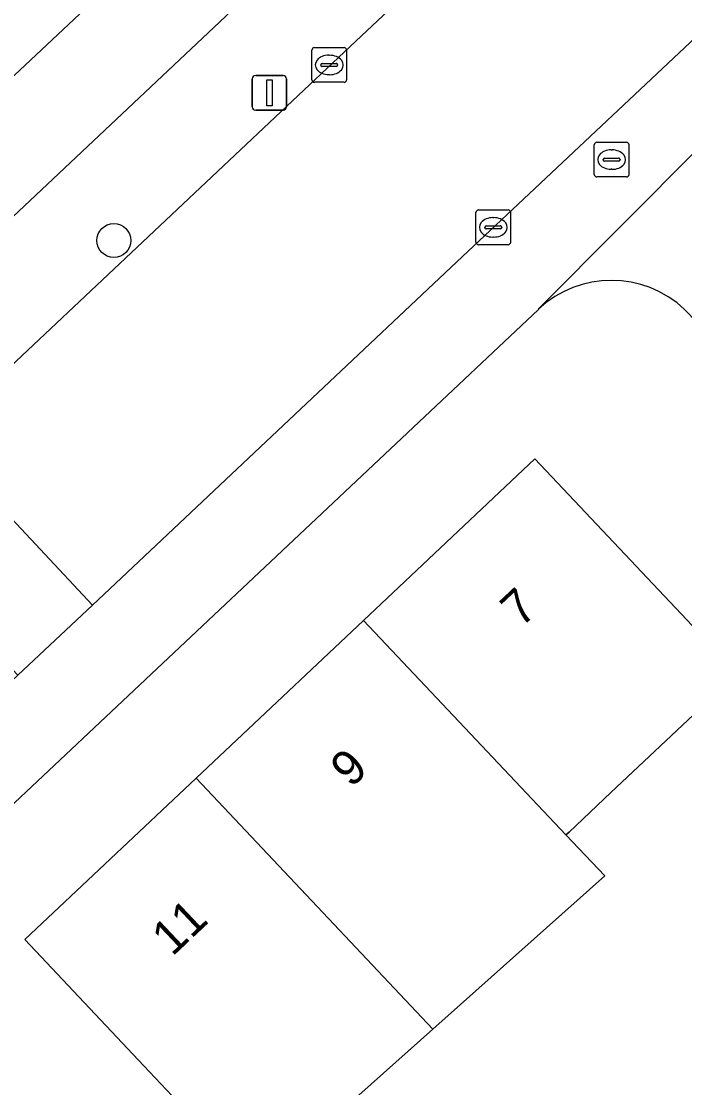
# Model space of a CAD drawing. Extents: x 159960 to 160866, y 382700 to 383354.
# Drawn here: x 160378.08 to 160397.17, y 383064.49 to 383095.2 of the extents above; entities that cross this region are included whole.
import ezdxf

# ---------------------------------------------------------------- set-up
doc = ezdxf.new("R2010")
doc.units = 0
for name, color, linetype in [('IMGEO_Boom', 7, 'Continuous'), ('IMGEO_Brandkraan', 7, 'Continuous'), ('IMGEO_Erf', 7, 'Continuous'), ('IMGEO_Kolk', 7, 'Continuous'), ('IMGEO_Lichtmast', 7, 'Continuous'), ('IMGEO_Pand', 7, 'Continuous'), ('IMGEO_Pand_nummerreeks', 7, 'Continuous'), ('IMGEO_Rijbaan_lokaal_open', 7, 'Continuous'), ('IMGEO_Voetpad_open', 7, 'Continuous')]:
    doc.layers.add(name, color=color, linetype=linetype)

msp = doc.modelspace()

# ---------------------------------------------------------------- linework, layer by layer
at = {"layer": 'IMGEO_Boom'}
msp.add_circle((160380.742, 383088.885), 0.489, dxfattribs=at)
at = {"layer": 'IMGEO_Brandkraan'}
for p, q in [((160394.639, 383091.715), (160395.491, 383091.715)), ((160394.564, 383090.789), (160394.564, 383091.641)), ((160395.052, 383091.495), (160395.077, 383091.495)), ((160395.565, 383091.641), (160395.565, 383090.789)), ((160394.823, 383091.209), (160394.823, 383091.221)), ((160395.261, 383091.172), (160394.863, 383091.172)), ((160394.866, 383091.258), (160395.264, 383091.258)), ((160395.307, 383091.221), (160395.307, 383091.209)), ((160395.075, 383090.935), (160395.05, 383090.935)), ((160395.491, 383090.715), (160394.639, 383090.715))]:
    msp.add_line(p, q, dxfattribs=at)
for points in [[(160394.639, 383091.715), (160395.491, 383091.715)], [(160394.564, 383090.789), (160394.564, 383091.641)], [(160395.565, 383091.641), (160395.565, 383090.789)], [(160395.491, 383090.715), (160394.639, 383090.715)]]:
    msp.add_lwpolyline(points, dxfattribs=at)
for centre, radius, start, end in [((160394.641, 383091.639), 0.0765, 91.552, 178.448), ((160394.641, 383091.639), 0.0765, 91.552, 178.448), ((160395.489, 383091.639), 0.0765, 1.552, 88.448), ((160395.489, 383091.639), 0.0765, 1.552, 88.448), ((160394.863, 383091.218), 0.0403, 85.8775, 175.7526), ((160394.86, 383091.208), 0.0366, 178.938, 274.7102), ((160395.264, 383091.215), 0.043, 264.8664, 352.4533), ((160395.268, 383091.22), 0.0386, 1.7309, 96.639), ((160394.641, 383090.791), 0.0765, 181.552, 268.448), ((160394.641, 383090.791), 0.0765, 181.552, 268.448), ((160395.489, 383090.791), 0.0765, 271.552, 358.448), ((160395.489, 383090.791), 0.0765, 271.552, 358.448)]:
    msp.add_arc(centre, radius, start, end, dxfattribs=at)
for centre, major_axis, ratio, start_param, end_param in [((160395.051, 383091.215), (-0.387, 0.002), 0.722429, 4.712389, 7.853982), ((160395.076, 383091.215), (-0.39, 0.002), 0.717154, 1.570796, 4.712389)]:
    msp.add_ellipse(centre, major_axis=major_axis, ratio=ratio, start_param=start_param, end_param=end_param, dxfattribs=at)
at = {"layer": 'IMGEO_Erf'}
for points in [[(160381.152, 383096.726), (160376.776, 383092.62), (160372.4, 383088.517), (160367.88, 383084.277), (160369.879, 383082.077), (160423.666, 383132.79)], [(160392.957, 383086.903), (160366.558, 383062.037)], [(160404.22, 383079.65), (160397.167, 383086.9)]]:
    msp.add_lwpolyline(points, dxfattribs=at)
msp.add_lwpolyline([(160378.176, 383068.752), (160383.106, 383073.4), (160387.927, 383077.945), (160392.859, 383082.595), (160398.683, 383076.418), (160395.046, 383072.988), (160393.839, 383071.85), (160393.751, 383071.767), (160394.866, 383070.584), (160389.921, 383066.171), (160384.864, 383061.658), (160381.606, 383065.114)], close=True, dxfattribs=at)
msp.add_arc((160395.06, 383084.668), 3.069, 46.6617, 133.2566, dxfattribs=at)
at = {"layer": 'IMGEO_Kolk'}
for p, q in [((160386.438, 383093.515), (160386.438, 383094.367)), ((160386.513, 383094.441), (160387.365, 383094.441)), ((160386.926, 383094.221), (160386.951, 383094.221)), ((160387.439, 383094.367), (160387.439, 383093.515)), ((160386.697, 383093.935), (160386.697, 383093.947)), ((160387.135, 383093.898), (160386.737, 383093.898)), ((160386.74, 383093.984), (160387.138, 383093.984)), ((160387.181, 383093.947), (160387.181, 383093.935)), ((160386.949, 383093.661), (160386.924, 383093.661)), ((160387.365, 383093.441), (160386.513, 383093.441)), ((160391.159, 383088.838), (160391.159, 383089.69)), ((160391.234, 383089.764), (160392.086, 383089.764)), ((160391.647, 383089.544), (160391.672, 383089.544)), ((160392.16, 383089.69), (160392.16, 383088.838)), ((160391.418, 383089.258), (160391.418, 383089.27)), ((160391.461, 383089.307), (160391.859, 383089.307)), ((160391.902, 383089.27), (160391.902, 383089.258)), ((160391.856, 383089.221), (160391.458, 383089.221)), ((160391.67, 383088.984), (160391.645, 383088.984)), ((160392.086, 383088.764), (160391.234, 383088.764))]:
    msp.add_line(p, q, dxfattribs=at)
for points in [[(160386.438, 383093.515), (160386.438, 383094.367)], [(160386.513, 383094.441), (160387.365, 383094.441)], [(160387.439, 383094.367), (160387.439, 383093.515)], [(160387.365, 383093.441), (160386.513, 383093.441)], [(160391.159, 383088.838), (160391.159, 383089.69)], [(160391.234, 383089.764), (160392.086, 383089.764)], [(160392.16, 383089.69), (160392.16, 383088.838)], [(160392.086, 383088.764), (160391.234, 383088.764)]]:
    msp.add_lwpolyline(points, dxfattribs=at)
for centre, radius, start, end in [((160386.515, 383094.365), 0.0765, 91.552, 178.448), ((160386.515, 383094.365), 0.0765, 91.552, 178.448), ((160387.363, 383094.365), 0.0765, 1.552, 88.448), ((160387.363, 383094.365), 0.0765, 1.552, 88.448), ((160386.737, 383093.944), 0.0403, 85.8775, 175.7526), ((160386.734, 383093.934), 0.0366, 178.938, 274.7102), ((160387.138, 383093.941), 0.043, 264.8664, 352.4533), ((160387.142, 383093.946), 0.0386, 1.7309, 96.639), ((160386.515, 383093.517), 0.0765, 181.552, 268.448), ((160386.515, 383093.517), 0.0765, 181.552, 268.448), ((160387.363, 383093.517), 0.0765, 271.552, 358.448), ((160387.363, 383093.517), 0.0765, 271.552, 358.448), ((160391.236, 383089.688), 0.0765, 91.552, 178.448), ((160391.236, 383089.688), 0.0765, 91.552, 178.448), ((160392.084, 383089.688), 0.0765, 1.552, 88.448), ((160392.084, 383089.688), 0.0765, 1.552, 88.448), ((160391.458, 383089.267), 0.0403, 85.8775, 175.7526), ((160391.455, 383089.257), 0.0366, 178.938, 274.7102), ((160391.859, 383089.264), 0.043, 264.8664, 352.4533), ((160391.863, 383089.269), 0.0386, 1.7309, 96.639), ((160391.236, 383088.84), 0.0765, 181.552, 268.448), ((160391.236, 383088.84), 0.0765, 181.552, 268.448), ((160392.084, 383088.84), 0.0765, 271.552, 358.448), ((160392.084, 383088.84), 0.0765, 271.552, 358.448)]:
    msp.add_arc(centre, radius, start, end, dxfattribs=at)
for centre, major_axis, ratio, start_param, end_param in [((160386.925, 383093.941), (-0.387, 0.002), 0.722429, 4.712389, 7.853982), ((160386.95, 383093.941), (-0.39, 0.002), 0.717154, 1.570796, 4.712389), ((160391.646, 383089.264), (-0.387, 0.002), 0.722429, 4.712389, 7.853982), ((160391.671, 383089.264), (-0.39, 0.002), 0.717154, 1.570796, 4.712389)]:
    msp.add_ellipse(centre, major_axis=major_axis, ratio=ratio, start_param=start_param, end_param=end_param, dxfattribs=at)
at = {"layer": 'IMGEO_Lichtmast'}
for p, q in [((160384.722, 383092.739), (160384.722, 383093.539)), ((160384.722, 383093.539), (160384.722, 383092.739)), ((160384.822, 383093.639), (160385.612, 383093.639)), ((160385.612, 383093.639), (160384.822, 383093.639)), ((160385.712, 383093.539), (160385.712, 383092.739)), ((160385.712, 383092.739), (160385.712, 383093.539)), ((160385.612, 383092.639), (160384.822, 383092.639)), ((160384.822, 383092.639), (160385.612, 383092.639))]:
    msp.add_line(p, q, dxfattribs=at)
msp.add_lwpolyline([(160385.142, 383093.514), (160385.292, 383093.514), (160385.292, 383092.764), (160385.142, 383092.764), (160385.142, 383093.514)], dxfattribs=at)
for centre, start, end in [((160384.822, 383093.539), 90, 180), ((160384.822, 383093.539), 90, 180), ((160385.612, 383093.539), 0, 90), ((160385.612, 383093.539), 360, 90), ((160384.822, 383092.739), 180, 270), ((160384.822, 383092.739), 180, 270), ((160385.612, 383092.739), 270, 0), ((160385.612, 383092.739), 270, 0)]:
    msp.add_arc(centre, 0.1, start, end, dxfattribs=at)
at = {"layer": 'IMGEO_Pand'}
for points in [[(160376.776, 383092.62), (160381.152, 383096.726), (160373.311, 383105.084), (160368.935, 383100.98), (160371.018, 383098.759)], [(160398.683, 383076.418), (160392.859, 383082.595), (160387.927, 383077.945), (160393.751, 383071.767), (160393.839, 383071.85), (160395.046, 383072.988)], [(160387.927, 383077.945), (160383.106, 383073.4), (160389.921, 383066.171), (160394.866, 383070.584), (160393.751, 383071.767)], [(160383.106, 383073.4), (160378.176, 383068.752), (160381.606, 383065.114), (160384.864, 383061.658), (160389.921, 383066.171)]]:
    msp.add_lwpolyline(points, close=True, dxfattribs=at)
at = {"layer": 'IMGEO_Rijbaan_lokaal_open'}
for points in [[(160403.552, 383100.436), (160405.554, 383102.316), (160415.821, 383111.942), (160411.292, 383116.793), (160405.8, 383111.613), (160397.4, 383103.731), (160393.269, 383099.855), (160387.865, 383094.781), (160375.599, 383083.221), (160380.124, 383078.379), (160390.773, 383088.421), (160397.489, 383094.742), (160399.709, 383096.829)], [(160375.599, 383083.221), (160373.431, 383081.176), (160377.981, 383076.364), (160380.124, 383078.379)]]:
    msp.add_lwpolyline(points, close=True, dxfattribs=at)
at = {"layer": 'IMGEO_Voetpad_open'}
for points in [[(160434.718, 383143.083), (160432.132, 383140.666), (160427.441, 383136.302), (160423.666, 383132.79), (160369.879, 383082.077), (160366.117, 383078.629), (160362.229, 383074.94), (160358.346, 383071.384), (160360.462, 383069.126), (160361.545, 383070.036), (160363.349, 383071.742), (160362.543, 383072.636), (160366.151, 383075.937), (160368.547, 383078.218), (160369.356, 383077.35), (160373.431, 383081.176), (160375.599, 383083.221), (160387.865, 383094.781), (160393.269, 383099.855), (160397.4, 383103.731), (160405.8, 383111.613), (160411.292, 383116.793)], [(160392.957, 383086.903), (160392.983, 383086.934), (160400.001, 383093.994), (160399.824, 383094.214), (160402.15, 383096.388), (160402.323, 383096.17), (160405.806, 383099.371), (160403.865, 383100.106), (160400.544, 383096.98), (160397.808, 383094.397), (160397.489, 383094.742), (160390.773, 383088.421), (160380.124, 383078.379), (160377.981, 383076.364), (160375.61, 383074.142), (160375.064, 383073.623), (160375.779, 383072.837), (160372.493, 383069.76), (160369.542, 383066.97), (160368.837, 383067.739), (160363.348, 383062.566), (160362.612, 383061.814)], [(160400.001, 383093.994), (160392.983, 383086.934), (160392.957, 383086.903)], [(160366.558, 383062.037), (160392.957, 383086.903)], [(160397.167, 383086.9), (160404.22, 383079.65), (160409.328, 383065.794), (160410.001, 383064.837), (160434.709, 383000), (160437.48, 382992.728), (160437.936, 382991.531), (160439.695, 382989.752), (160448.148, 382980.26), (160450.916, 382981.972)]]:
    msp.add_lwpolyline(points, dxfattribs=at)
msp.add_arc((160395.06, 383084.668), 3.069, 46.6617, 133.2566, dxfattribs=at)

# ---------------------------------------------------------------- texts
at = {"layer": 'IMGEO_Pand_nummerreeks'}
for s, rotation, p in [('7', 43.3156, (160392.46, 383077.713)), ('9', 43.3156, (160387.566, 383073.098)), ('11', 43.3133, (160382.421, 383068.247))]:
    msp.add_text(s, height=1, rotation=rotation, dxfattribs=at).set_placement(p)

doc.saveas('drawing.dxf')
